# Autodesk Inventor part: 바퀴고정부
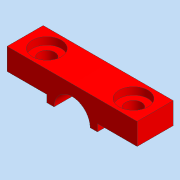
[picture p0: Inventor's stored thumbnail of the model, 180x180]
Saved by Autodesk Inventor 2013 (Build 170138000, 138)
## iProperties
Company: 한국ATC센터
Created: 2015-05
Part Number: 바퀴고정부
Document SubType Name: 모델링
Designer: KYOUNG IL JANG
Vendor: CBT Solutions
Material: 일반
d0: 1.000 ul
Author: KYOUNG IL JANG
Comments: 파생
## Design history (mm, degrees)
derived "바퀴고정부.ipt" dims count "d0" = 1
node "솔리드1"
node "솔리드 본체"
node "곡면 본체"
feature "솔리드1::바퀴고정부.ipt" dims count "d0" = 1
tag "피쳐 태그1"
